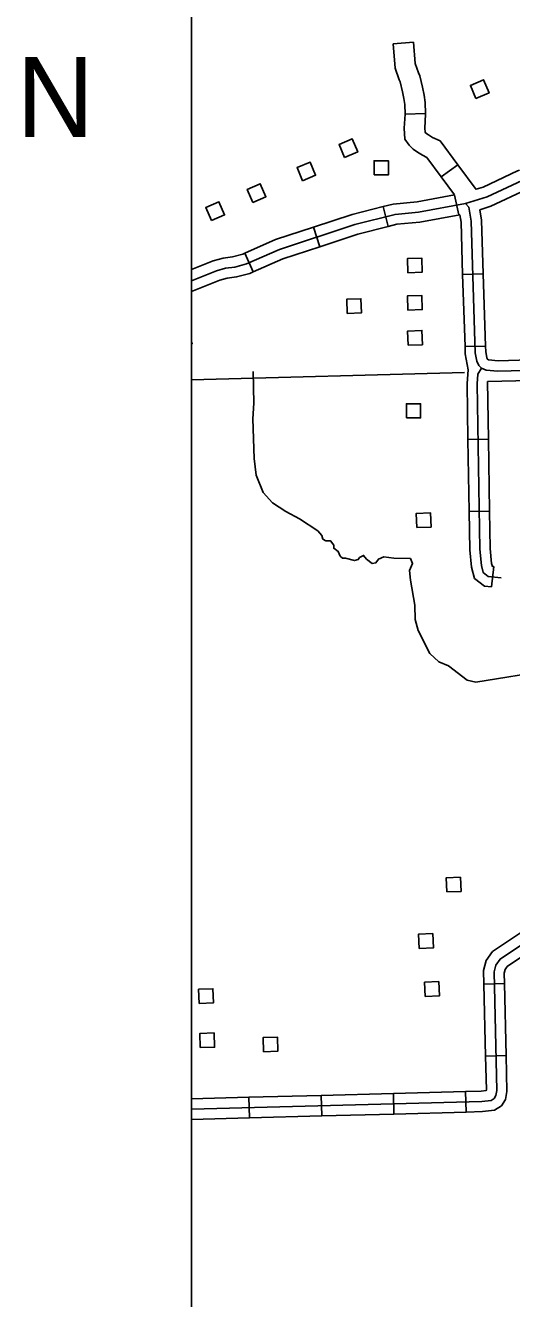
# Model space of a CAD drawing. Extents: x -0.3 to 2.65, y 0 to 1.9.
# Drawn here: x 0.3702 to 0.4128, y 0.3259 to 0.4374 of the extents above; entities that cross this region are included whole.
import ezdxf

# ---------------------------------------------------------------- set-up
doc = ezdxf.new("R2010")
doc.units = 0
for name, color, linetype in [('DSN_DRFT_DNC', 7, 'Continuous'), ('Level 14', 7, 'Continuous'), ('Level 15', 7, 'Continuous'), ('Level 19', 7, 'Continuous'), ('Level 20', 7, 'Continuous'), ('Level 6', 7, 'Continuous'), ('SHET_Annotations', 7, 'Continuous')]:
    doc.layers.add(name, color=color, linetype=linetype)

msp = doc.modelspace()

# ---------------------------------------------------------------- linework, layer by layer
at = {"layer": 'DSN_DRFT_DNC'}
msp.add_lwpolyline([(0.38477, 0.54167), (1.0319, 0.54167), (1.0319, 0.1443), (0.38477, 0.1443)], close=True, dxfattribs=at)
at = {"layer": 'Level 14'}
msp.add_lwpolyline([(0.39016, 0.4071), (0.39021, 0.40433), (0.39012, 0.40294), (0.39023, 0.39948), (0.39041, 0.39802), (0.39104, 0.3965), (0.39186, 0.3956), (0.39302, 0.39484), (0.3942, 0.3942), (0.39581, 0.39316), (0.39615, 0.39273), (0.39625, 0.39242), (0.39651, 0.39227), (0.39693, 0.39226), (0.3972, 0.39189), (0.39721, 0.39163), (0.3976, 0.39134), (0.39777, 0.39094), (0.39798, 0.39075), (0.39823, 0.39076), (0.39901, 0.39055), (0.39935, 0.39063), (0.39947, 0.39081), (0.39982, 0.391), (0.40007, 0.39067), (0.40056, 0.39028), (0.4009, 0.39036), (0.40112, 0.39068), (0.4016, 0.39086), (0.40247, 0.39076), (0.40392, 0.39074), (0.40411, 0.39029), (0.40382, 0.38969), (0.40393, 0.38882), (0.40431, 0.38665), (0.40433, 0.38538), (0.40458, 0.38443), (0.40561, 0.3824), (0.4064, 0.38169), (0.40724, 0.38133), (0.40887, 0.38007), (0.40965, 0.3799), (0.41613, 0.38094)], dxfattribs=at)
at = {"layer": 'Level 15'}
for p, q in [((0.40239, 0.43577), (0.40417, 0.43593)), ((0.40344, 0.42963), (0.40524, 0.42968)), ((0.40661, 0.42413), (0.40806, 0.42519)), ((0.40814, 0.4208), (0.40777, 0.42254)), ((0.40198, 0.41979), (0.40153, 0.42153)), ((0.39598, 0.41801), (0.39542, 0.41972)), ((0.39015, 0.41581), (0.38943, 0.41746)), ((0.40848, 0.41558), (0.41028, 0.41564)), ((0.40869, 0.40927), (0.41048, 0.40932)), ((0.40895, 0.40114), (0.41074, 0.40117)), ((0.40905, 0.39483), (0.41084, 0.39486)), ((0.41102, 0.38824), (0.4112, 0.39002)), ((0.41214, 0.35352), (0.41035, 0.35348)), ((0.41229, 0.34721), (0.41049, 0.34717)), ((0.38979, 0.34356), (0.38476, 0.34342)), ((0.38984, 0.34176), (0.38979, 0.34356)), ((0.39615, 0.34193), (0.3961, 0.34373)), ((0.40247, 0.3421), (0.40242, 0.3439)), ((0.40878, 0.34227), (0.40874, 0.34407)), ((0.38984, 0.34176), (0.38476, 0.34163))]:
    msp.add_line(p, q, dxfattribs=at)
for points in [[(0.40239, 0.43577), (0.40257, 0.43366), (0.40294, 0.43264), (0.40301, 0.43244), (0.40322, 0.43159), (0.40335, 0.43098), (0.40342, 0.43048), (0.40344, 0.42963)], [(0.40417, 0.43593), (0.40434, 0.43405), (0.40463, 0.43325), (0.40473, 0.43297), (0.40497, 0.43199), (0.40512, 0.43129), (0.40521, 0.43063), (0.40524, 0.42968)], [(0.38476, 0.41504), (0.38694, 0.41592), (0.38772, 0.41614), (0.38854, 0.41624), (0.38956, 0.41651), (0.39245, 0.41778), (0.39906, 0.41995), (0.40257, 0.42085), (0.40461, 0.42105), (0.40873, 0.4218), (0.41063, 0.42239), (0.41369, 0.42383), (0.41637, 0.42519), (0.42106, 0.42801), (0.42272, 0.42911), (0.42437, 0.43042), (0.42555, 0.43162), (0.42664, 0.43251), (0.42753, 0.43297), (0.42875, 0.4333), (0.43043, 0.43342), (0.43979, 0.43364)], [(0.40344, 0.42963), (0.40344, 0.42963), (0.40338, 0.42839), (0.40343, 0.42744), (0.40379, 0.4269), (0.40414, 0.42657), (0.40452, 0.42631), (0.40497, 0.42602), (0.40534, 0.42584), (0.40661, 0.42413)], [(0.40524, 0.42968), (0.40524, 0.42961), (0.40517, 0.4284), (0.40519, 0.42804), (0.40527, 0.42797), (0.40551, 0.4278), (0.40584, 0.42759), (0.40651, 0.42728), (0.40806, 0.42519)], [(0.40806, 0.42519), (0.40966, 0.42303)], [(0.40967, 0.42305), (0.41029, 0.42324), (0.41329, 0.42465), (0.41345, 0.42473)], [(0.40661, 0.42413), (0.40777, 0.42257)], [(0.40153, 0.42153), (0.40241, 0.42175), (0.40449, 0.42196), (0.40776, 0.42255)], [(0.40998, 0.42126), (0.41094, 0.42156), (0.41407, 0.42304), (0.41426, 0.42313)], [(0.39542, 0.41972), (0.39881, 0.42083), (0.40153, 0.42153)], [(0.40873, 0.4218), (0.40902, 0.42147), (0.40922, 0.42026), (0.40958, 0.40874), (0.40972, 0.408), (0.4099, 0.40761), (0.41012, 0.40739), (0.41055, 0.40722), (0.41157, 0.40713), (0.44098, 0.40786)], [(0.40998, 0.42126), (0.41013, 0.42035), (0.41028, 0.41564)], [(0.40198, 0.41979), (0.40273, 0.41998), (0.40474, 0.42018), (0.40823, 0.42082)], [(0.40823, 0.42082), (0.40834, 0.42017), (0.40848, 0.41558)], [(0.38943, 0.41746), (0.39212, 0.41864), (0.39542, 0.41972)], [(0.39598, 0.41801), (0.39931, 0.41911), (0.40198, 0.41979)], [(0.39015, 0.41581), (0.39276, 0.41696), (0.39598, 0.41801)], [(0.38476, 0.41603), (0.38665, 0.41678), (0.38753, 0.41703), (0.38836, 0.41714), (0.38925, 0.41738), (0.38943, 0.41746)], [(0.38476, 0.41409), (0.38723, 0.41508), (0.38789, 0.41527), (0.38871, 0.41537), (0.38985, 0.41568), (0.39015, 0.41581)], [(0.40848, 0.41558), (0.40869, 0.40927)], [(0.41028, 0.41564), (0.41048, 0.40932)], [(0.40869, 0.40927), (0.40871, 0.40865), (0.40896, 0.40723)], [(0.41048, 0.40932), (0.4105, 0.40884), (0.4106, 0.40828), (0.41065, 0.40817), (0.41076, 0.40812), (0.4116, 0.40804), (0.41433, 0.40811)], [(0.40896, 0.40723), (0.40887, 0.40606), (0.40895, 0.40114)], [(0.41012, 0.40739), (0.40982, 0.40687), (0.40975, 0.40603), (0.40998, 0.39154), (0.41012, 0.39012), (0.41028, 0.3895), (0.41073, 0.38915), (0.41186, 0.38904)], [(0.41066, 0.40623), (0.41438, 0.40632)], [(0.41066, 0.40623), (0.41074, 0.40117)], [(0.40895, 0.40114), (0.40905, 0.39483)], [(0.41074, 0.40117), (0.41084, 0.39486)], [(0.40905, 0.39483), (0.4091, 0.39149), (0.40925, 0.38996), (0.40951, 0.38899), (0.41039, 0.3883), (0.41102, 0.38824)], [(0.41084, 0.39486), (0.4109, 0.39159), (0.41102, 0.39028), (0.41109, 0.39004), (0.4112, 0.39002)], [(0.4423, 0.37211), (0.44013, 0.37215), (0.43955, 0.37209), (0.43895, 0.37186), (0.43829, 0.37151), (0.43082, 0.36649), (0.42781, 0.3646), (0.42098, 0.36166), (0.4194, 0.36075), (0.41176, 0.35566), (0.41139, 0.35514), (0.41123, 0.35455), (0.41148, 0.34415), (0.4114, 0.34371), (0.41124, 0.34346), (0.41097, 0.34329), (0.41016, 0.34319), (0.38476, 0.34251)], [(0.4146, 0.35865), (0.41111, 0.35632), (0.41055, 0.35553), (0.41032, 0.35465), (0.41035, 0.35348)], [(0.4156, 0.35716), (0.41238, 0.35502), (0.4122, 0.35476), (0.41212, 0.35444), (0.41214, 0.35352)], [(0.41035, 0.35348), (0.41049, 0.34717)], [(0.41214, 0.35352), (0.41229, 0.34721)], [(0.41049, 0.34717), (0.41056, 0.34422), (0.41055, 0.34416), (0.41009, 0.3441), (0.40874, 0.34407)], [(0.41229, 0.34721), (0.41236, 0.34408), (0.41224, 0.34338), (0.41187, 0.34281), (0.41127, 0.34244), (0.41023, 0.34231), (0.40878, 0.34227)], [(0.3961, 0.34373), (0.38979, 0.34356)], [(0.40242, 0.3439), (0.3961, 0.34373)], [(0.40874, 0.34407), (0.40242, 0.3439)], [(0.40878, 0.34227), (0.40247, 0.3421)], [(0.39615, 0.34193), (0.38984, 0.34176)], [(0.40247, 0.3421), (0.39615, 0.34193)]]:
    msp.add_lwpolyline(points, dxfattribs=at)
at = {"layer": 'Level 19'}
for points in [[(0.40965, 0.43099), (0.40916, 0.43214), (0.41031, 0.43263), (0.4108, 0.43148)], [(0.39815, 0.42583), (0.39767, 0.42697), (0.39882, 0.42746), (0.3993, 0.42632)], [(0.39447, 0.42379), (0.39399, 0.42494), (0.39513, 0.42543), (0.39562, 0.42428)], [(0.40074, 0.4243), (0.40074, 0.42555), (0.40199, 0.42555), (0.40199, 0.4243)], [(0.39012, 0.4219), (0.38963, 0.42304), (0.39078, 0.42353), (0.39127, 0.42239)], [(0.3865, 0.42031), (0.38601, 0.42146), (0.38716, 0.42195), (0.38765, 0.4208)], [(0.4037, 0.41573), (0.40365, 0.41698), (0.4049, 0.41702), (0.40494, 0.41578)], [(0.39838, 0.41218), (0.39834, 0.41342), (0.39958, 0.41347), (0.39963, 0.41222)], [(0.4037, 0.41247), (0.40366, 0.41372), (0.4049, 0.41376), (0.40495, 0.41252)], [(0.40372, 0.4094), (0.40367, 0.41064), (0.40492, 0.41069), (0.40496, 0.40944)], [(0.40356, 0.40304), (0.40356, 0.40428), (0.40481, 0.40428), (0.40481, 0.40304)], [(0.40447, 0.39343), (0.40443, 0.39467), (0.40568, 0.39472), (0.40572, 0.39347)], [(0.40709, 0.36154), (0.40705, 0.36278), (0.40829, 0.36283), (0.40834, 0.36158)], [(0.40467, 0.3566), (0.40462, 0.35784), (0.40587, 0.35789), (0.40592, 0.35664)], [(0.4052, 0.3524), (0.40515, 0.35364), (0.4064, 0.35369), (0.40645, 0.35244)], [(0.38542, 0.35177), (0.38538, 0.35302), (0.38663, 0.35306), (0.38667, 0.35182)], [(0.38553, 0.34791), (0.38549, 0.34915), (0.38674, 0.3492), (0.38678, 0.34795)], [(0.39107, 0.34755), (0.39102, 0.34879), (0.39227, 0.34884), (0.39231, 0.34759)]]:
    msp.add_lwpolyline(points, close=True, dxfattribs=at)
msp.add_lwpolyline([(0.38476, 0.40968), (0.38482, 0.40953), (0.38476, 0.40951)], dxfattribs=at)
at = {"layer": 'Level 20'}
msp.add_line((0.40866, 0.407), (0.38476, 0.40637), dxfattribs=at)
at = {"layer": 'Level 6'}
msp.add_line((0.38476, 0.54164), (0.38476, 0.14427), dxfattribs=at)

# ---------------------------------------------------------------- texts
at = {"layer": 'SHET_Annotations'}
msp.add_text('N', height=0.007, dxfattribs=at).set_placement((0.36946, 0.42763))

doc.saveas('drawing.dxf')
